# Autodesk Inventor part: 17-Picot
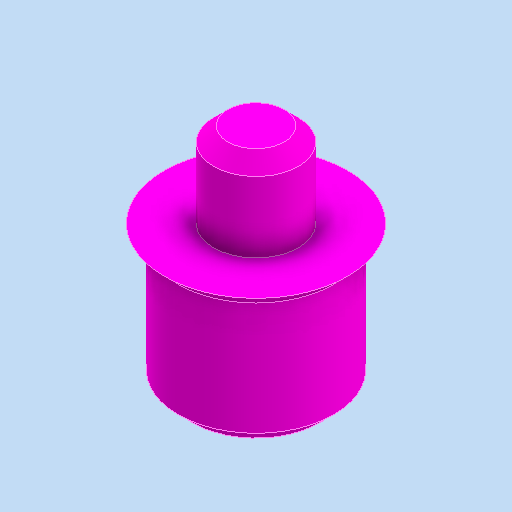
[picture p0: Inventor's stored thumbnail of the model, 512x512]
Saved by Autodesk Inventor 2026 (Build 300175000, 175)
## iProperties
Created: 2025-12
Part Number: 17-Picot
Material: Générique
Document SubType Name: Modeling
Designer: thierry.jost
Density: 1 g/cm^3
Appearance: Magenta
Author: thierry.jost
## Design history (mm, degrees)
sketch "Esquisse1"
  geometry: L1 (11.343, 0)-(11.343, 3); L2 (11.343, 3)-(5.343, 3); L3 (5.343, 3)-(5.343, 6.5); L4 (5.343, 6.5)-(4.343, 6.5); L5 (4.343, 6.5)-(4.343, 5.5); L6 (4.343, 5.5)-(-4.657, 5.5); L7 (-4.657, 5.5)-(-4.657, 0); L8 (-4.657, 0)-(11.343, 0); 1 further point
  constraints: 16 end point, 7 perpendicular, 1 vertical
  dimensions: "d0" = 11 diameter of L6 L8; "d1" = 6 diameter of L2 L8; "d2" = 1 distance of L3.end L4.end; "d3" = 6 distance of L1.end L2.end; "d4" = 9 distance of L5.end L6.end; "d9" = 13 diameter of L4 L8
revolve "Révolution1" sketch "Esquisse1" stored, may be unused: angle "d5" = 90 deg
chamfer "Chanfrein1" distance "d6" = 1; stored, may be unused: second distance "d7" = 2, angle "d8" = 45 deg
chamfer "Chanfrein2" distance "d10" = 1; stored, may be unused: second distance "d11" = 2, angle "d12" = 45 deg
node "Solide1"
